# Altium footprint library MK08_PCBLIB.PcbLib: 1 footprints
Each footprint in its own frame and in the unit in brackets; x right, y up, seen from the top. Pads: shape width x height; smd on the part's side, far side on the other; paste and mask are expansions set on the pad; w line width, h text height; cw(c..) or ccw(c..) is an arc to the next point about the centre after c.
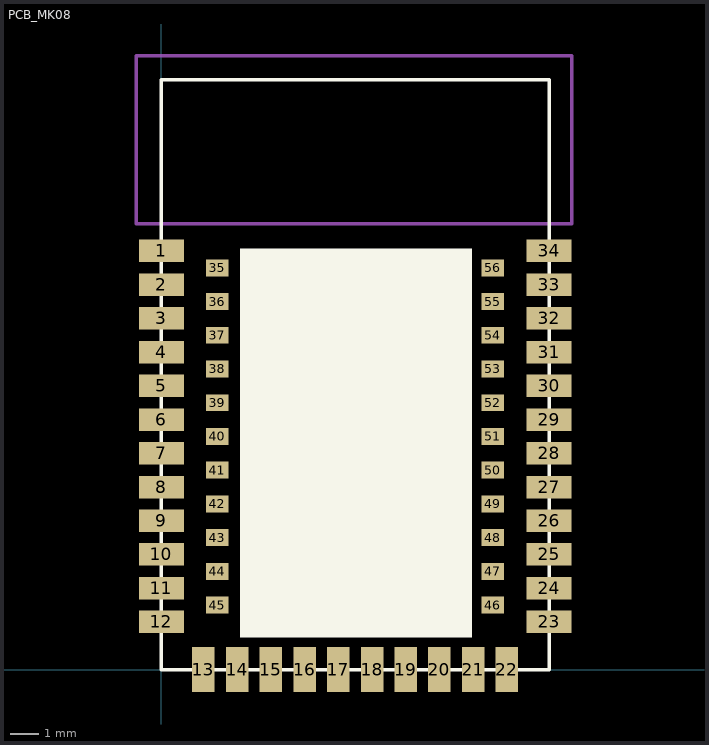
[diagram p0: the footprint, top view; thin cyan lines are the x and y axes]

## PCB_MK08 [mm] "21*13.8mm"
height 2
pads (56):
  rect 1.6x0.8 smd: 1(0,14.9) 2(0,13.7) 3(0,12.5) 4(0,11.3) 5(0,10.1) 6(0,8.9) 7(0,7.7) 8(0,6.5) 9(0,5.3) 10(0,4.1) 11(0,2.9) 12(0,1.7) 23(13.8,1.7) 24(13.8,2.9) 25(13.8,4.1) 26(13.8,5.3) 27(13.8,6.5) 28(13.8,7.7) 29(13.8,8.9) 30(13.8,10.1) 31(13.8,11.3) 32(13.8,12.5) 33(13.8,13.7) 34(13.8,14.9)
  rect 0.8x1.6 smd: 13(1.5,0) 14(2.7,0) 15(3.9,0) 16(5.1,0) 17(6.3,0) 18(7.5,0) 19(8.7,0) 20(9.9,0) 21(11.1,0) 22(12.3,0)
  rect 0.8x0.6 smd: 35(2,14.3) 36(2,13.1) 37(2,11.9) 38(2,10.7) 39(2,9.5) 40(2,8.3) 41(2,7.1) 42(2,5.9) 43(2,4.7) 44(2,3.5) 45(2,2.3) 46(11.8,2.3) 47(11.8,3.5) 48(11.8,4.7) 49(11.8,5.9) 50(11.8,7.1) 51(11.8,8.3) 52(11.8,9.5) 53(11.8,10.7) 54(11.8,11.9) 55(11.8,13.1) 56(11.8,14.3)
Top Overlay:
  rectangle: 2.794,1.143 11.049,14.986
  lines w0.127: 0,0 0,21 13.8,21 13.8,0 0,0
Mechanical 2:
  lines w0.127: -0.889,15.875 14.605,15.875 14.605,21.844 -0.889,21.844 -0.889,15.875
  text "No ground pad" at 3.556,18.288 h0.51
